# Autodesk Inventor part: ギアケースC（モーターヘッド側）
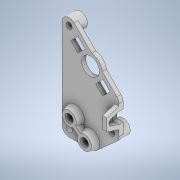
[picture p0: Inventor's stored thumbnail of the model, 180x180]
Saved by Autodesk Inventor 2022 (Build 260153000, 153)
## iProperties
Created: 2024-09
Part Number: ギアケースC（モーターヘッド側）
Material: 一般
Document SubType Name: Modeling
Designer: shimizu
Density: 1 g/cm^3
Appearance: 既定
Author: shimizu
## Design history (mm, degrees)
sketch "スケッチ1"
  geometry: L1 (14, 22)-(14, 8); L2 (0, -4.5)-(-10.5, -4.5); L3 (-14, -1)-(-14, 43); L4 (12.826, 5.385)-(2.991, -3.363); L5 (-8.025, 45.475)-(0.634, 36.816); L6 (5.816, 31.634)-(12.975, 24.475); L7 (-7.676, 38.676)-(8.458, 22.542); L8 (-6.116, 40.652)-(-9.652, 37.116); L9 (-2.581, 37.116)-(-6.116, 33.581); L10 (9.652, 24.884)-(6.116, 21.348); L11 (6.116, 28.419)-(2.581, 24.884); L12 (-9.652, 37.116)-(-6.116, 33.581); L13 (2.581, 24.884)-(6.116, 21.348); L14 (-6.116, 40.652)-(-2.581, 37.116); L15 (6.116, 28.419)-(9.652, 24.884); C1 r 4.35 at (0, 31); A1 r 3.5 centre (-10.5, 43) between (-8.025, 45.475) and (-14, 43); A2 r 4.5 centre (0, 0) between (0, -4.5) and (2.991, -3.363); A3 r 3.5 centre (10.5, 8) between (12.826, 5.385) and (14, 8); A4 r 5.85 centre (0, 31) between (5.816, 31.634) and (0.634, 36.816); A5 r 3.5 centre (10.5, 22) between (14, 22) and (12.975, 24.475); A6 r 3.5 centre (-10.5, -1) between (-14, -1) and (-10.5, -4.5); 1 further point
  constraints: 30 end point, 12 point on circle, 11 tangent, 9 parallel, 7 centre point, 2 perpendicular, 1 coincident, 1 concentric, 1 equal radius, 1 point on line, 1 vertical alignment
  dimensions: "d0" = 7 diameter of A1; "d1" = 43 vertical distance of point (0, 0) A1.centre; "d2" = 9 diameter of A2; "d3" = 14 distance from line of L3 point (0, 0); "d6" = 14 distance from line of L1 point (0, 0); "d7" = 7 diameter of A3; "d8" = 8 vertical distance of point (0, 0) A3.centre; "d9" = 11.7 diameter of A4; "d10" = 31 distance of point (0, 0) A4.centre; "d11" = 8.7 diameter of C1; "d12" = 3.5 radius of A5; "d15" = 5 distance between parallel lines of L9 L8; "d16" = 6.15 distance from line of A4.centre L9; "d17" = 5 distance between parallel lines of L10 L11; "d18" = 6.15 distance from line of A4.centre L11; "d19" = 2.5 distance between parallel lines of L7 L14; "d20" = 2.5 distance between parallel lines of L12 L7
extrude "押し出し1" new body sketch "スケッチ1" distance "d21" = 2; taper "d22" = 0 deg
sketch "スケッチ2"
  geometry: C1 r 3.5 at (10.5, 43); C2 r 3.5 at (-10.5, 8); C3 r 3.5 at (10.5, -1); A1 r 3.5 centre (10.5, 43) between (14, 43) and (8.025, 45.475) reference; A2 r 3.5 centre (-10.5, 8) between (-14, 8) and (-12.826, 5.385) reference; A3 r 3.5 centre (10.5, -1) between (10.5, -4.5) and (14, -1) reference; 1 further point
  constraints: 6 concentric, 3 centre point
extrude "押し出し2" join sketch "スケッチ2" distance "d23" = 3.5; taper "d24" = 0 deg
sketch "スケッチ3"
  geometry: C1 r 3 at (0, 0); C2 r 3 at (0, -44); C3 r 3 at (-21, -35); C4 r 3.5 at (0, 0) reference; C5 r 3.5 at (0, -44) reference; C6 r 3.5 at (-21, -35) reference; 1 further point
  constraints: 3 centre point, 3 concentric, 2 equal radius
  dimensions: "d25" = 6 diameter of C1
extrude "押し出し3" cut sketch "スケッチ3" distance "d26" = 0.5; taper "d27" = 0 deg
sketch "スケッチ4"
  geometry: C1 r 4.5 at (-7.5, 6.5); C2 r 4.5 at (0, 0); 1 further point
  constraints: 2 centre point, 1 coincident, 1 equal radius
  dimensions: "d28" = 9 diameter of C2; "d29" = 6.5 vertical distance of point (0, 0) C1.centre; "d30" = 7.5 horizontal distance of point (0, 0) C1.centre
extrude "押し出し4" join sketch "スケッチ4" distance "d31" = 3; taper "d32" = -18.4 deg
sketch "スケッチ5"
  geometry: L1 (-7.5, 6.5)-(0, 0); L2 (-6.845, 7.256)-(0.655, 0.756); L3 (-8.155, 5.744)-(-0.655, -0.756); L4 (-6.845, 7.256)-(-8.155, 5.744); L5 (0.655, 0.756)-(-0.655, -0.756); C1 r 1.49 at (-7.5, 6.5); C2 r 2.402 at (0, 0); C3 r 3.502 at (-7.5, 6.5) reference; C4 r 3.502 at (0, 0) reference; 5 further points
  constraints: 10 end point, 3 parallel, 2 centre point, 2 coincident, 2 concentric, 2 midpoint, 1 perpendicular
  dimensions: "d33" = 1 distance between parallel lines of L1 L2; "d34" = 1 distance between parallel lines of L3 L1
extrude "押し出し5" join sketch "スケッチ5" stored distance "d35" = 3; taper "d36" = 0 deg
sketch "スケッチ6"
  geometry: C1 r 1.5 at (10.5, 8); C2 r 1.5 at (-10.5, 43); C3 r 1.5 at (-10.5, -1); C4 r 2.05 at (-7.5, 6.5); C5 r 2.05 at (0, 0); A1 r 3.5 centre (-10.5, 43) between (-8.025, 45.475) and (-14, 43) reference; A2 r 3.5 centre (10.5, 8) between (12.826, 5.385) and (14, 8) reference; A3 r 3.5 centre (-10.5, -1) between (-14, -1) and (-10.5, -4.5) reference; A4 r 3.502 centre (-7.5, 6.5) between (-4.309, 5.058) and (-5.619, 3.546) reference; A5 r 3.502 centre (0, 0) between (-3.191, 1.442) and (-1.881, 2.954) reference; 1 further point
  constraints: 5 centre point, 5 concentric, 3 equal radius
  dimensions: "d37" = 3 diameter of C2; "d38" = 4.1 diameter of C4
extrude "押し出し6" cut sketch "スケッチ6" extent not by distance; stored distance "d39" = 3; taper "d40" = 0 deg
sketch "スケッチ7"
  geometry: L1 (-19.54, 8)-(30.961, 8); L2 (-8, 11)-(-8, 5); L3 (-8, 11)-(-2, 13); L4 (-2, 35)-(-2, -9) reference; L5 (-8, 5)-(-2, 3); L6 (-5.974, 9.423)-(-2, 10.748); L7 (-5.974, 6.577)-(-2, 5.252); A1 r 1.5 centre (-5.5, 8) between (-5.974, 9.423) and (-5.974, 6.577); 1 further point
  constraints: 12 end point, 4 point on line, 2 parallel, 2 point on circle, 2 tangent, 1 centre point, 1 horizontal, 1 midpoint, 1 perpendicular, 1 vertical
  dimensions: "d41" = 16 distance from line of point (0, -8) L1; "d42" = 3 distance from line of L1 L2.start; "d43" = 3 distance from line of L1 L2.end; "d44" = 5 distance from line of L1 L3.end; "d45" = 5 distance from line of L1 L5.end; "d46" = 6 distance between parallel lines of L4 L2; "d47" = 3 diameter of A1; "d48" = 3.5 distance from line of L4 A1.centre
extrude "押し出し7" join sketch "スケッチ7" distance "d49" = 2; taper "d50" = 0 deg
sketch "スケッチ8"
  geometry: L1 (-2, 35)-(-2, -9) reference; L2 (0, 0)-(0, 14) reference; L3 (-2, 10.748)-(0, 10.748); L4 (0, 10.748)-(0, 5.252); L5 (0, 5.252)-(-2, 5.252); L6 (-2, 5.252)-(-2, 10.748); 2 further points
  constraints: 8 end point, 2 parallel, 1 horizontal, 1 perpendicular, 1 point on line
extrude "押し出し8" cut sketch "スケッチ8" distance "d51" = 3; taper "d52" = 0 deg
node "ソリッド1"
other parameters: "d5" = 45 deg, "d13" = 2.5, "d14" = 2.5
